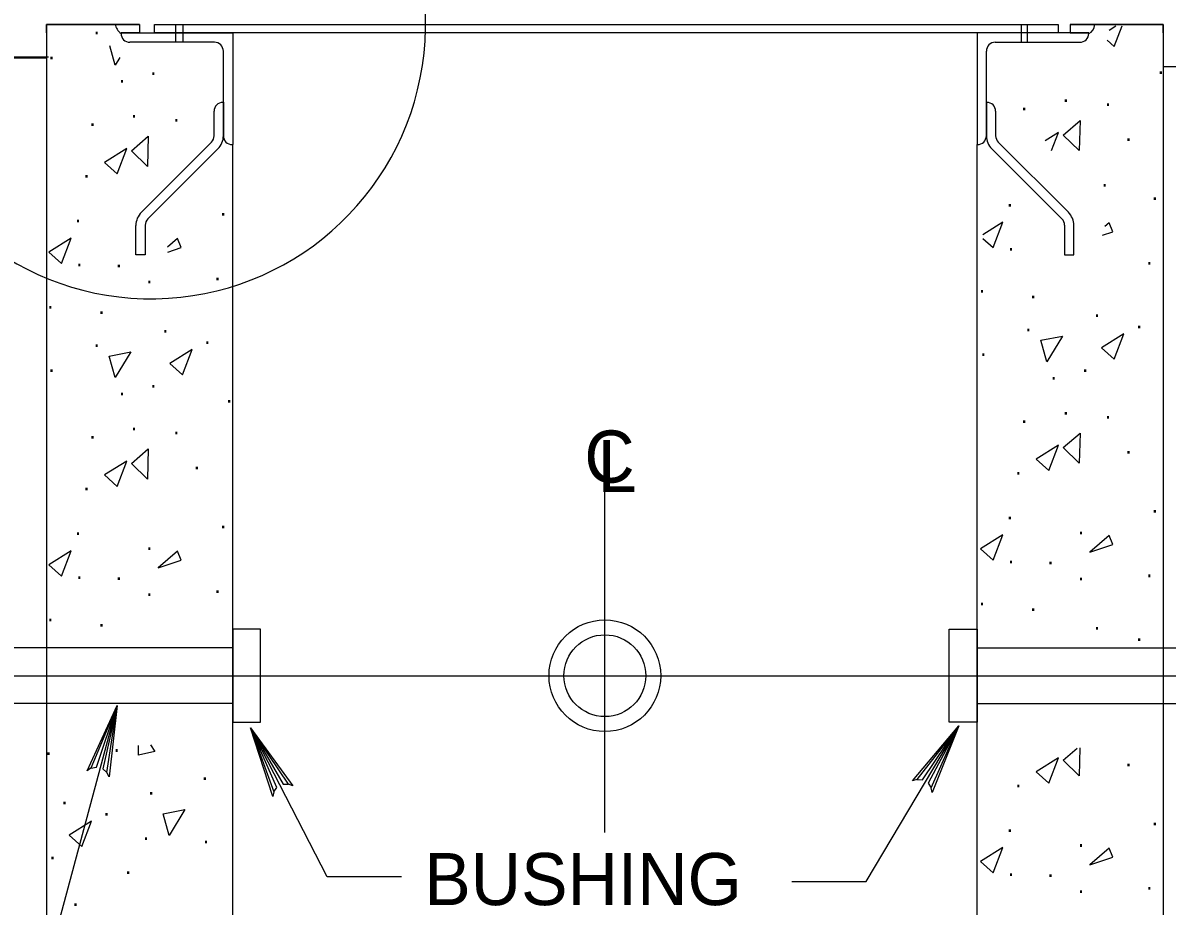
# Model space of a CAD drawing. Extents: x 638447 to 639352, y 298406 to 299000.
# Drawn here: x 638720.2 to 638794, y 298717.1 to 298774.1 of the extents above; entities that cross this region are included whole.
import ezdxf

# ---------------------------------------------------------------- set-up
doc = ezdxf.new("R2010")
doc.units = 0
doc.layers.add('2', color=7, linetype='Continuous')
doc.layers.add('3', color=7, linetype='Continuous')

msp = doc.modelspace()

# ---------------------------------------------------------------- linework, layer by layer
at = {"layer": '2'}
for p, q in [((638721.754375, 298774.004), (638721.754375, 298690.004)), ((638730.062375, 298773.982), (638730.062375, 298772.89)), ((638730.530375, 298773.982), (638730.530375, 298772.89)), ((638784.608375, 298773.982), (638784.608375, 298772.89)), ((638784.982375, 298773.982), (638784.982375, 298772.89)), ((638726.554375, 298773.448), (638733.754375, 298773.448)), ((638733.754375, 298773.448), (638733.754375, 298766.248)), ((638788.954375, 298773.448), (638781.754375, 298773.448)), ((638781.754375, 298773.448), (638781.754375, 298766.248)), ((638732.578375, 298772.848), (638727.130375, 298772.848)), ((638782.930375, 298772.848), (638788.378375, 298772.848)), ((638721.880375, 298771.898), (638704.232375, 298771.898)), ((638733.154375, 298766.824), (638733.154375, 298772.272)), ((638782.354375, 298766.824), (638782.354375, 298772.272)), ((638793.754375, 298771.288), (638812.986375, 298771.288)), ((638733.154375, 298768.976), (638733.154375, 298766.824)), ((638782.354375, 298768.976), (638782.354375, 298766.824)), ((638732.554375, 298766.814), (638732.554375, 298768.4)), ((638782.954375, 298766.814), (638782.954375, 298768.4)), ((638727.864375, 298761.886), (638732.384375, 298766.406)), ((638732.802375, 298765.976), (638728.282375, 298761.456)), ((638782.704375, 298765.976), (638787.224375, 298761.456)), ((638787.642375, 298761.886), (638783.122375, 298766.406)), ((638727.514375, 298759.136), (638727.514375, 298761.038)), ((638728.114375, 298761.048), (638728.114375, 298759.136)), ((638787.394375, 298761.048), (638787.394375, 298759.136)), ((638787.994375, 298759.136), (638787.994375, 298761.038)), ((638728.114375, 298759.136), (638727.514375, 298759.136)), ((638787.394375, 298759.136), (638787.994375, 298759.136)), ((638757.754375, 298721.9), (638757.754375, 298746.826)), ((638721.754375, 298733.804), (638715.754375, 298733.804)), ((638733.754375, 298733.804), (638721.754375, 298733.804)), ((638781.754375, 298733.804), (638793.754375, 298733.804)), ((638793.754375, 298733.804), (638799.754375, 298733.804)), ((638708.694375, 298732.004), (638808.624375, 298732.004)), ((638757.754375, 298732.004), (638757.754375, 298732.004)), ((638757.754375, 298732.004), (638757.754375, 298732.004)), ((638721.754375, 298730.204), (638715.754375, 298730.204)), ((638733.754375, 298730.204), (638721.754375, 298730.204)), ((638781.754375, 298730.204), (638793.754375, 298730.204)), ((638793.754375, 298730.204), (638799.754375, 298730.204))]:
    msp.add_line(p, q, dxfattribs=at)
for points in [[(638721.754375, 298773.448), (638721.754375, 298774.004), (638727.754375, 298774.004), (638727.754375, 298773.448), (638726.554375, 298773.448)], [(638727.754375, 298774.004), (638721.754375, 298774.004), (638721.754375, 298702.004), (638733.754375, 298702.004), (638733.754375, 298766.248)], [(638726.554375, 298774.004), (638727.754375, 298774.004)], [(638787.754375, 298774.004), (638793.754375, 298774.004), (638793.754375, 298702.004), (638781.754375, 298702.004), (638781.754375, 298766.248)], [(638781.754375, 298774.004), (638781.754375, 298774.004)], [(638793.754375, 298773.448), (638793.754375, 298774.004), (638787.754375, 298774.004), (638787.754375, 298773.448), (638788.954375, 298773.448)], [(638790.712375, 298773.89), (638790.272375, 298773.616)], [(638790.602375, 298772.58), (638791.108375, 298773.906)], [(638726.178375, 298771.382), (638725.826375, 298772.618)], [(638790.154375, 298772.982), (638790.602375, 298772.58)], [(638704.492375, 298771.844), (638721.768375, 298771.844)], [(638726.468375, 298771.862), (638726.178375, 298771.382)], [(638787.002375, 298767.024), (638786.140375, 298766.486)], [(638786.564375, 298765.88), (638787.002375, 298767.024)], [(638783.414375, 298761.24), (638782.136375, 298760.442)], [(638782.790375, 298759.608), (638783.414375, 298761.24)], [(638790.266375, 298761.204), (638790.000375, 298760.974)], [(638790.518375, 298760.628), (638790.266375, 298761.204)], [(638730.186375, 298760.186), (638729.546375, 298759.634)], [(638730.438375, 298759.61), (638730.186375, 298760.186)], [(638782.134375, 298760.196), (638782.790375, 298759.608)], [(638789.832375, 298760.4), (638790.518375, 298760.628)], [(638729.564375, 298759.32), (638730.438375, 298759.61)], [(638714.282375, 298697.684), (638717.588375, 298697.684), (638726.312375, 298730.088)], [(638724.616375, 298726.036), (638724.964375, 298726.108), (638726.312375, 298730.088), (638724.616375, 298726.036), (638724.372375, 298725.872), (638726.312375, 298730.088), (638725.388375, 298725.994), (638725.648375, 298725.762), (638726.312375, 298730.088), (638725.786375, 298725.478), (638725.648375, 298725.762)], [(638744.642375, 298719.032), (638739.842375, 298719.032), (638734.896375, 298728.634)], [(638736.406375, 298724.508), (638736.612375, 298724.798), (638734.896375, 298728.634), (638736.406375, 298724.508), (638736.338375, 298724.222), (638734.896375, 298728.634), (638737.000375, 298725.002), (638737.348375, 298725.008), (638734.896375, 298728.634), (638737.642375, 298724.894), (638737.348375, 298725.008)], [(638769.810375, 298718.742), (638774.610375, 298718.742), (638780.574375, 298728.78)], [(638777.876375, 298725.312), (638778.232375, 298725.29), (638780.574375, 298728.78), (638777.876375, 298725.312), (638777.598375, 298725.218), (638780.574375, 298728.78), (638778.610375, 298725.068), (638778.800375, 298724.778), (638780.574375, 298728.78), (638778.860375, 298724.468), (638778.800375, 298724.778)], [(638727.690375, 298726.878), (638727.678375, 298727.502)], [(638728.460375, 298727.54), (638728.734375, 298727.118)], [(638728.734375, 298727.118), (638727.690375, 298726.878)], [(638787.314375, 298726.548), (638788.218375, 298727.332)], [(638788.390375, 298727.348), (638788.346375, 298725.54)], [(638788.346375, 298725.54), (638787.314375, 298726.548)]]:
    msp.add_lwpolyline(points, dxfattribs=at)
for points in [[(638728.710375, 298773.448), (638728.710375, 298774.004), (638786.978375, 298774.004), (638786.978375, 298773.448)], [(638787.314375, 298766.868), (638788.394375, 298767.804), (638788.346375, 298765.86)], [(638727.234375, 298765.85), (638728.314375, 298766.786), (638728.266375, 298764.842)], [(638726.922375, 298766.006), (638725.482375, 298765.106), (638726.298375, 298764.374)], [(638723.334375, 298760.222), (638721.894375, 298759.322), (638722.710375, 298758.59)], [(638791.226375, 298754.052), (638789.786375, 298753.152), (638790.602375, 298752.42)], [(638785.862375, 298753.632), (638787.266375, 298753.908), (638786.258375, 298752.24)], [(638725.782375, 298752.614), (638727.186375, 298752.89), (638726.178375, 298751.222)], [(638731.146375, 298753.034), (638729.706375, 298752.134), (638730.522375, 298751.402)], [(638787.314375, 298746.708), (638788.394375, 298747.644), (638788.346375, 298745.7)], [(638787.002375, 298746.864), (638785.562375, 298745.964), (638786.378375, 298745.232)], [(638727.234375, 298745.69), (638728.314375, 298746.626), (638728.266375, 298744.682)], [(638726.922375, 298745.846), (638725.482375, 298744.946), (638726.298375, 298744.214)], [(638783.414375, 298741.08), (638781.974375, 298740.18), (638782.790375, 298739.448)], [(638790.518375, 298740.468), (638790.266375, 298741.044), (638789.030375, 298739.976)], [(638723.334375, 298740.062), (638721.894375, 298739.162), (638722.710375, 298738.43)], [(638730.438375, 298739.45), (638730.186375, 298740.026), (638728.950375, 298738.958)], [(638735.554375, 298729.004), (638735.554375, 298735.004), (638733.754375, 298735.004), (638733.754375, 298729.004)], [(638779.954375, 298729.004), (638779.954375, 298735.004), (638781.754375, 298735.004), (638781.754375, 298729.004)], [(638787.002375, 298726.704), (638785.562375, 298725.804), (638786.378375, 298725.072)], [(638729.262375, 298723.098), (638730.666375, 298723.374), (638729.658375, 298721.706)], [(638724.642375, 298722.63), (638723.202375, 298721.73), (638724.018375, 298720.998)], [(638783.414375, 298720.92), (638781.974375, 298720.02), (638782.790375, 298719.288)], [(638790.518375, 298720.308), (638790.266375, 298720.884), (638789.030375, 298719.816)]]:
    msp.add_lwpolyline(points, close=True, dxfattribs=at)
for radius in [3.6, 2.637448]:
    msp.add_circle((638757.753701, 298732.003748), radius, dxfattribs=at)
for centre, radius, start, end in [((638728.491221, 298774.003748), 17.699271, 110.26046667, 71.742925), ((638727.093508, 298774.178243), 0.927976, 189.25816944, 234.42950556), ((638788.745698, 298773.975562), 0.590014, 290.64261389, 356.09181111), ((638727.129701, 298773.423428), 0.576, 180, 270), ((638788.377701, 298773.423428), 0.576, 270, 0), ((638732.577701, 298772.271428), 0.576, 0, 90), ((638782.929701, 298772.271428), 0.576, 90, 180), ((638733.129653, 298768.398932), 0.576, 90, 180), ((638782.377749, 298768.398932), 0.576, 0, 90), ((638731.977653, 298766.813519), 0.576, 315, 0), ((638731.953653, 298766.823444), 1.2, 315, 0), ((638733.729701, 298766.823428), 0.576, 180, 270), ((638781.777701, 298766.823428), 0.576, 270, 0), ((638783.553749, 298766.823444), 1.2, 180, 225), ((638783.529749, 298766.813519), 0.576, 180, 225), ((638728.713653, 298761.037875), 1.2, 135, 180), ((638728.689653, 298761.047801), 0.576, 135, 180), ((638786.817749, 298761.047801), 0.576, 0, 45), ((638786.793749, 298761.037875), 1.2, 0, 45)]:
    msp.add_arc(centre, radius, start, end, dxfattribs=at)

# ---------------------------------------------------------------- texts
for p in [(638724.774375, 298773.35), (638724.774375, 298773.35), (638721.870375, 298771.754), (638726.406375, 298770.242), (638728.434375, 298770.734), (638793.398375, 298770.792), (638787.266375, 298769.004), (638789.990375, 298768.74), (638727.186375, 298767.986), (638784.590375, 298768.464), (638724.510375, 298767.446), (638729.910375, 298767.722), (638791.310375, 298766.484), (638724.126375, 298764.11), (638789.776375, 298763.52825), (638783.654375, 298762.248), (638793.014375, 298762.68), (638723.574375, 298761.23), (638732.934375, 298761.662), (638783.738375, 298759.416), (638723.658375, 298758.398), (638726.202375, 298758.326), (638792.654375, 298758.516), (638728.170375, 298757.294), (638732.574375, 298757.498), (638781.866375, 298756.692), (638785.166375, 298756.344), (638721.786375, 298755.674), (638725.086375, 298755.326), (638789.282375, 298755.132), (638729.202375, 298754.114), (638784.854375, 298754.208), (638784.854375, 298754.208), (638791.994375, 298754.4), (638724.774375, 298753.19), (638724.774375, 298753.19), (638731.914375, 298753.382), (638781.950375, 298752.612), (638721.870375, 298751.594), (638786.486375, 298751.1), (638788.514375, 298751.592), (638728.434375, 298750.574), (638726.406375, 298750.082), (638733.318375, 298749.614), (638787.266375, 298748.844), (638784.590375, 298748.304), (638789.990375, 298748.58), (638724.510375, 298747.286), (638727.186375, 298747.826), (638729.910375, 298747.562), (638791.310375, 298746.324), (638731.230375, 298745.306), (638784.206375, 298744.968), (638724.126375, 298743.95), (638783.654375, 298742.088), (638793.014375, 298742.52), (638732.934375, 298741.502), (638723.574375, 298741.07), (638788.250375, 298741.128), (638728.170375, 298740.11), (638783.738375, 298739.256), (638786.282375, 298739.184), (638792.654375, 298738.356), (638723.658375, 298738.238), (638726.202375, 298738.166), (638788.250375, 298738.152), (638728.170375, 298737.134), (638732.574375, 298737.338), (638781.866375, 298736.532), (638785.166375, 298736.184), (638721.786375, 298735.514), (638725.086375, 298735.166), (638789.282375, 298734.972), (638791.994375, 298734.24), (638721.666375, 298726.89), (638726.070375, 298727.094), (638791.310375, 298726.164), (638731.746375, 298725.27), (638728.290375, 298724.334), (638784.206375, 298724.808), (638722.698375, 298723.71), (638725.410375, 298722.978), (638793.014375, 298722.36), (638727.954375, 298721.418), (638783.654375, 298721.928), (638731.830375, 298721.19), (638788.250375, 298720.968), (638721.930375, 298720.17), (638726.814375, 298719.21), (638783.738375, 298719.096), (638786.282375, 298719.024), (638788.250375, 298717.992), (638792.654375, 298718.196), (638723.406375, 298717.158)]:
    msp.add_text('.', height=1.116, dxfattribs=at).set_placement(p)
at = {"layer": '3'}
for s, p in [('C', (638756.428375, 298744.454)), ('L', (638757.296375, 298743.848)), ('BUSHING', (638746.110375, 298717.21))]:
    msp.add_text(s, height=3.359988, dxfattribs=at).set_placement(p)

doc.saveas('drawing.dxf')
